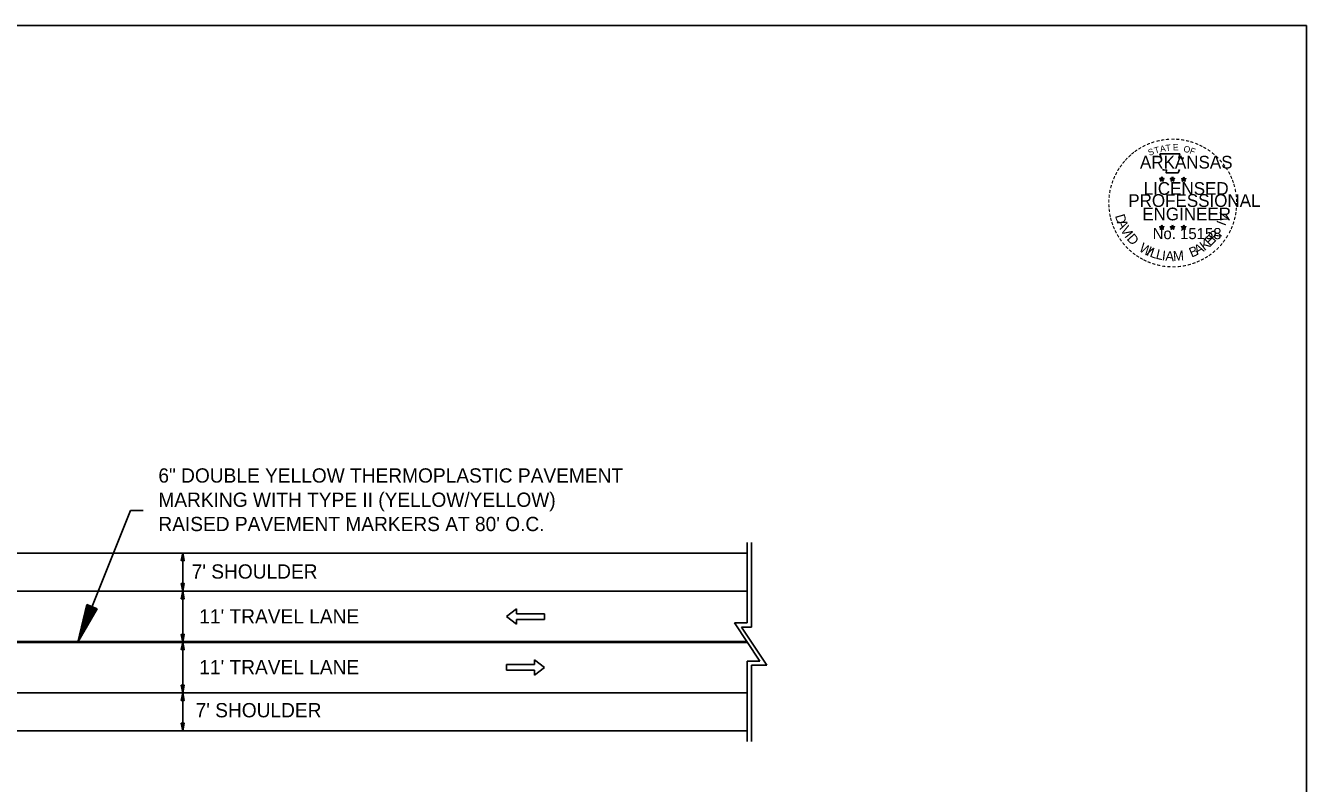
# Model space of a CAD drawing. Extents: x 1372926 to 1373096, y 381240 to 381790.
# Drawn here: x 1372995.2 to 1373096, y 381400.5 to 381460.2 of the extents above; entities that cross this region are included whole.
import ezdxf

# ---------------------------------------------------------------- set-up
doc = ezdxf.new("R2010")
doc.units = 0
for name, color, linetype in [('Default', 7, 'Continuous'), ('DSN_DRFT_Junk-No-Plot', 7, 'Continuous'), ('R_Draft', 7, 'Continuous'), ('SHET_Border-Text', 7, 'Continuous')]:
    doc.layers.add(name, color=color, linetype=linetype)

msp = doc.modelspace()

# ---------------------------------------------------------------- linework, layer by layer
at = {"layer": 'Default'}
for p, q in [((1373003.46, 381422), (1372999.31, 381411.64)), ((1373004.46, 381422), (1373003.46, 381422)), ((1373051.97, 381419.48), (1373051.97, 381413.14)), ((1373052.31, 381419.48), (1373052.31, 381412.81)), ((1373000.01, 381414.6), (1372999.31, 381411.64)), ((1373000.84, 381414.26), (1372999.31, 381411.64)), ((1373000.07, 381414.57), (1372999.49, 381412.11)), ((1373000.77, 381414.29), (1372999.49, 381412.11)), ((1373000.15, 381414.54), (1372999.68, 381412.59)), ((1373000.7, 381414.32), (1372999.68, 381412.59)), ((1373000.22, 381414.51), (1372999.87, 381413.05)), ((1373000.63, 381414.35), (1372999.87, 381413.05)), ((1373000.84, 381414.26), (1373000.01, 381414.6)), ((1373000.29, 381414.48), (1373000.06, 381413.52)), ((1373000.56, 381414.37), (1373000.06, 381413.52)), ((1373000.36, 381414.45), (1373000.25, 381413.99)), ((1373000.49, 381414.4), (1373000.25, 381413.99)), ((1373033.05, 381413.64), (1373033.82, 381414.24)), ((1373033.82, 381413.87), (1373033.82, 381414.24)), ((1373033.82, 381413.87), (1373036.03, 381413.87)), ((1373036.03, 381413.42), (1373036.03, 381413.87)), ((1373033.82, 381413.04), (1373033.05, 381413.64)), ((1373033.82, 381413.42), (1373036.03, 381413.42)), ((1373033.82, 381413.04), (1373033.82, 381413.42)), ((1373051.97, 381413.14), (1373050.97, 381413.14)), ((1373052.97, 381410.14), (1373050.97, 381413.14)), ((1373053.53, 381409.81), (1373051.53, 381412.81)), ((1373052.31, 381412.81), (1373051.53, 381412.81)), ((1373035.25, 381409.87), (1373033.05, 381409.87)), ((1373033.05, 381409.87), (1373033.05, 381409.42)), ((1373035.25, 381410.24), (1373035.25, 381409.87)), ((1373035.25, 381410.24), (1373036.03, 381409.64)), ((1373051.97, 381403.81), (1373051.97, 381410.14)), ((1373051.97, 381410.14), (1373052.97, 381410.14)), ((1373052.31, 381403.81), (1373052.31, 381409.81)), ((1373052.31, 381409.81), (1373053.53, 381409.81)), ((1373035.25, 381409.42), (1373033.05, 381409.42)), ((1373036.03, 381409.64), (1373035.25, 381409.04)), ((1373035.25, 381409.42), (1373035.25, 381409.04))]:
    msp.add_line(p, q, dxfattribs=at)
msp.add_lwpolyline([(1372925.97, 381460.17), (1372925.97, 381350.17), (1373095.97, 381350.17), (1373095.97, 381460.17)], close=True, dxfattribs=at)
at = {"layer": 'DSN_DRFT_Junk-No-Plot'}
msp.add_line((1373007.57, 381417.64), (1373007.57, 381405.64), dxfattribs=at)
for points in [[(1372925.97, 381460.17), (1373095.97, 381460.17), (1373095.97, 381350.17), (1372925.97, 381350.17)], [(1372925.97, 381460.17), (1372925.97, 381350.17), (1373095.97, 381350.17), (1373095.97, 381460.17)]]:
    msp.add_lwpolyline(points, close=True, dxfattribs=at)
for points in [[(1373007.57, 381418.65), (1373007.45, 381418.05), (1373007.69, 381418.05), (1373007.57, 381418.65), (1373007.57, 381417.45)], [(1373007.57, 381415.64), (1373007.69, 381416.24), (1373007.45, 381416.24), (1373007.57, 381415.64), (1373007.57, 381416.84)], [(1373007.57, 381415.64), (1373007.45, 381415.04), (1373007.69, 381415.04), (1373007.57, 381415.64), (1373007.57, 381414.44)], [(1373007.57, 381411.64), (1373007.69, 381412.24), (1373007.45, 381412.24), (1373007.57, 381411.64), (1373007.57, 381412.84)], [(1373007.57, 381411.64), (1373007.45, 381411.04), (1373007.69, 381411.04), (1373007.57, 381411.64), (1373007.57, 381410.44)], [(1373007.57, 381407.64), (1373007.69, 381408.24), (1373007.45, 381408.24), (1373007.57, 381407.64), (1373007.57, 381408.84)], [(1373007.57, 381407.64), (1373007.45, 381407.04), (1373007.69, 381407.04), (1373007.57, 381407.64), (1373007.57, 381406.44)], [(1373007.57, 381404.64), (1373007.69, 381405.24), (1373007.45, 381405.24), (1373007.57, 381404.64), (1373007.57, 381405.84)]]:
    msp.add_lwpolyline(points, dxfattribs=at)
at = {"layer": 'R_Draft'}
for p, q in [((1372975.58, 381418.64), (1373051.97, 381418.64)), ((1372975.58, 381415.64), (1373051.97, 381415.64)), ((1372975.55, 381411.69), (1373051.94, 381411.69)), ((1372975.62, 381411.59), (1373052.01, 381411.59)), ((1372975.58, 381407.64), (1373051.97, 381407.64)), ((1372975.58, 381404.64), (1373051.97, 381404.64))]:
    msp.add_line(p, q, dxfattribs=at)
at = {"layer": 'SHET_Border-Text'}
for p, q in [((1373084.43, 381448.13), (1373084.6, 381448.07)), ((1373084.43, 381448.13), (1373084.56, 381448.11)), ((1373084.43, 381448.13), (1373084.55, 381448.07)), ((1373084.5, 381447.93), (1373084.6, 381448.07)), ((1373084.5, 381447.93), (1373084.56, 381448.05)), ((1373084.5, 381447.93), (1373084.6, 381448.03)), ((1373084.6, 381448.26), (1373084.58, 381448.13)), ((1373084.6, 381448.07), (1373084.6, 381448.26)), ((1373084.6, 381448.26), (1373084.63, 381448.13)), ((1373084.78, 381448.13), (1373084.6, 381448.07)), ((1373084.71, 381447.93), (1373084.6, 381448.07)), ((1373084.71, 381447.93), (1373084.6, 381448.03)), ((1373084.78, 381448.13), (1373084.63, 381448.11)), ((1373084.71, 381447.93), (1373084.64, 381448.07)), ((1373084.78, 381448.13), (1373084.67, 381448.08)), ((1373085.26, 381448.13), (1373085.44, 381448.07)), ((1373085.26, 381448.13), (1373085.39, 381448.11)), ((1373085.26, 381448.13), (1373085.38, 381448.07)), ((1373085.33, 381447.93), (1373085.44, 381448.07)), ((1373085.33, 381447.93), (1373085.39, 381448.05)), ((1373085.33, 381447.93), (1373085.44, 381448.03)), ((1373085.44, 381448.26), (1373085.42, 381448.13)), ((1373085.44, 381448.07), (1373085.44, 381448.26)), ((1373085.44, 381448.26), (1373085.46, 381448.13)), ((1373085.61, 381448.13), (1373085.44, 381448.07)), ((1373085.54, 381447.93), (1373085.44, 381448.07)), ((1373085.54, 381447.93), (1373085.44, 381448.03)), ((1373085.61, 381448.13), (1373085.47, 381448.11)), ((1373085.54, 381447.93), (1373085.48, 381448.07)), ((1373085.61, 381448.13), (1373085.51, 381448.08)), ((1373086.15, 381448.12), (1373086.32, 381448.07)), ((1373086.15, 381448.12), (1373086.27, 381448.1)), ((1373086.15, 381448.12), (1373086.26, 381448.06)), ((1373086.21, 381447.92), (1373086.32, 381448.07)), ((1373086.21, 381447.92), (1373086.28, 381448.04)), ((1373086.21, 381447.92), (1373086.32, 381448.03)), ((1373086.32, 381448.25), (1373086.3, 381448.12)), ((1373086.32, 381448.07), (1373086.32, 381448.25)), ((1373086.32, 381448.25), (1373086.34, 381448.13)), ((1373086.49, 381448.12), (1373086.32, 381448.07)), ((1373086.43, 381447.92), (1373086.32, 381448.07)), ((1373086.43, 381447.92), (1373086.32, 381448.03)), ((1373086.49, 381448.12), (1373086.35, 381448.1)), ((1373086.43, 381447.92), (1373086.36, 381448.07)), ((1373086.49, 381448.12), (1373086.39, 381448.07)), ((1373084.43, 381444.34), (1373084.6, 381444.29)), ((1373084.43, 381444.34), (1373084.55, 381444.32)), ((1373084.43, 381444.34), (1373084.55, 381444.28)), ((1373084.49, 381444.14), (1373084.6, 381444.29)), ((1373084.49, 381444.14), (1373084.56, 381444.26)), ((1373084.49, 381444.14), (1373084.6, 381444.25)), ((1373084.6, 381444.47), (1373084.58, 381444.34)), ((1373084.6, 381444.29), (1373084.6, 381444.47)), ((1373084.6, 381444.47), (1373084.63, 381444.35)), ((1373084.77, 381444.34), (1373084.6, 381444.29)), ((1373084.71, 381444.14), (1373084.6, 381444.29)), ((1373084.71, 381444.14), (1373084.6, 381444.25)), ((1373084.77, 381444.34), (1373084.63, 381444.32)), ((1373084.71, 381444.14), (1373084.64, 381444.28)), ((1373084.77, 381444.34), (1373084.67, 381444.29)), ((1373085.26, 381444.34), (1373085.44, 381444.29)), ((1373085.26, 381444.34), (1373085.39, 381444.32)), ((1373085.26, 381444.34), (1373085.38, 381444.28)), ((1373085.33, 381444.14), (1373085.44, 381444.29)), ((1373085.33, 381444.14), (1373085.39, 381444.26)), ((1373085.33, 381444.14), (1373085.43, 381444.25)), ((1373085.44, 381444.47), (1373085.42, 381444.34)), ((1373085.54, 381444.14), (1373085.43, 381444.25)), ((1373085.44, 381444.29), (1373085.44, 381444.47)), ((1373085.44, 381444.47), (1373085.46, 381444.35)), ((1373085.61, 381444.34), (1373085.44, 381444.29)), ((1373085.54, 381444.14), (1373085.44, 381444.29)), ((1373085.61, 381444.34), (1373085.47, 381444.32)), ((1373085.54, 381444.14), (1373085.47, 381444.28)), ((1373085.61, 381444.34), (1373085.51, 381444.29)), ((1373086.14, 381444.34), (1373086.32, 381444.28)), ((1373086.14, 381444.34), (1373086.27, 381444.32)), ((1373086.14, 381444.34), (1373086.26, 381444.28)), ((1373086.21, 381444.13), (1373086.32, 381444.28)), ((1373086.21, 381444.13), (1373086.27, 381444.26)), ((1373086.21, 381444.13), (1373086.32, 381444.24)), ((1373086.32, 381444.47), (1373086.3, 381444.34)), ((1373086.32, 381444.28), (1373086.32, 381444.47)), ((1373086.32, 381444.47), (1373086.34, 381444.34)), ((1373086.49, 381444.34), (1373086.32, 381444.28)), ((1373086.43, 381444.13), (1373086.32, 381444.28)), ((1373086.43, 381444.13), (1373086.32, 381444.24)), ((1373086.49, 381444.34), (1373086.35, 381444.31)), ((1373086.43, 381444.13), (1373086.36, 381444.28)), ((1373086.49, 381444.34), (1373086.39, 381444.29))]:
    msp.add_line(p, q, dxfattribs=at)
for points in [[(1373084.45, 381450.07), (1373084.58, 381449.66)], [(1373086.2, 381449.61), (1373086.28, 381449.75), (1373085.93, 381449.74), (1373086.01, 381450.07), (1373084.45, 381450.07)], [(1373084.6, 381448.26), (1373084.71, 381447.93), (1373084.43, 381448.13), (1373084.78, 381448.13), (1373084.5, 381447.93), (1373084.6, 381448.26)], [(1373084.7, 381448.86), (1373084.7, 381448.81), (1373084.98, 381448.8), (1373084.95, 381448.57), (1373085.88, 381448.57), (1373085.99, 381448.84)], [(1373085.44, 381448.26), (1373085.54, 381447.93), (1373085.26, 381448.13), (1373085.61, 381448.13), (1373085.33, 381447.93), (1373085.44, 381448.26)], [(1373086.32, 381448.25), (1373086.43, 381447.92), (1373086.15, 381448.12), (1373086.49, 381448.12), (1373086.21, 381447.92), (1373086.32, 381448.25)], [(1373084.6, 381444.47), (1373084.71, 381444.14), (1373084.43, 381444.34), (1373084.77, 381444.34), (1373084.49, 381444.14), (1373084.6, 381444.47)], [(1373085.44, 381444.47), (1373085.54, 381444.14), (1373085.26, 381444.34), (1373085.61, 381444.34), (1373085.33, 381444.14), (1373085.44, 381444.47)], [(1373086.32, 381444.47), (1373086.43, 381444.13), (1373086.14, 381444.34), (1373086.49, 381444.34), (1373086.21, 381444.13), (1373086.32, 381444.47)]]:
    msp.add_lwpolyline(points, dxfattribs=at)
for centre, radius in [((1373084.6, 381448.07), 0.0861), ((1373084.6, 381448.07), 0.0723), ((1373084.6, 381448.07), 0.0579), ((1373084.6, 381448.07), 0.0495), ((1373084.6, 381448.07), 0.0374), ((1373084.6, 381448.07), 0.0248), ((1373084.6, 381448.07), 0.0148), ((1373085.44, 381448.07), 0.0861), ((1373085.44, 381448.07), 0.0723), ((1373085.44, 381448.07), 0.0579), ((1373085.44, 381448.07), 0.0495), ((1373085.44, 381448.07), 0.0374), ((1373085.44, 381448.07), 0.0248), ((1373085.44, 381448.07), 0.0148), ((1373086.32, 381448.07), 0.0861), ((1373086.32, 381448.07), 0.0723), ((1373086.32, 381448.07), 0.0579), ((1373086.32, 381448.07), 0.0495), ((1373086.32, 381448.07), 0.0374), ((1373086.32, 381448.07), 0.0248), ((1373086.32, 381448.07), 0.0148), ((1373084.6, 381444.29), 0.0861), ((1373084.6, 381444.29), 0.0723), ((1373084.6, 381444.29), 0.0579), ((1373084.6, 381444.29), 0.0495), ((1373084.6, 381444.29), 0.0374), ((1373084.6, 381444.29), 0.0248), ((1373084.6, 381444.29), 0.0148), ((1373085.44, 381444.29), 0.0861), ((1373085.44, 381444.29), 0.0723), ((1373085.44, 381444.29), 0.0579), ((1373085.44, 381444.29), 0.0495), ((1373085.44, 381444.29), 0.0374), ((1373085.44, 381444.29), 0.0248), ((1373085.44, 381444.29), 0.0148), ((1373086.32, 381444.28), 0.0861), ((1373086.32, 381444.28), 0.0723), ((1373086.32, 381444.28), 0.0579), ((1373086.32, 381444.28), 0.0495), ((1373086.32, 381444.28), 0.0374), ((1373086.32, 381444.28), 0.0248), ((1373086.32, 381444.28), 0.0148)]:
    msp.add_circle(centre, radius, dxfattribs=at)

# ---------------------------------------------------------------- texts
at = {"layer": 'Default'}
for s, p in [('6" DOUBLE YELLOW THERMOPLASTIC PAVEMENT', (1373005.65, 381424.19)), ('MARKING WITH TYPE II (YELLOW/YELLOW)', (1373005.65, 381422.28)), ("RAISED PAVEMENT MARKERS AT 80' O.C.", (1373005.65, 381420.37))]:
    msp.add_text(s, height=1.125, dxfattribs=at).set_placement(p)
at = {"layer": 'R_Draft'}
for s, p in [("7' SHOULDER", (1373008.27, 381416.63)), ("11' TRAVEL LANE", (1373008.87, 381413.1)), ("11' TRAVEL LANE", (1373008.87, 381409.1)), ("7' SHOULDER", (1373008.58, 381405.71))]:
    msp.add_text(s, height=1.125, dxfattribs=at).set_placement(p)
at = {"layer": 'SHET_Border-Text'}
for s, height, rotation, p in [('-', 0.8, 19.1761, (1373083.82, 381450.63)), ('-', 0.8, 13.6302, (1373084.2, 381450.75)), ('-', 0.8, 10.2193, (1373084.54, 381450.83)), ('-', 0.8, 5.8968, (1373084.9, 381450.89)), ('-', 0.8, 0.1862, (1373085.29, 381450.92)), ('-', 0.8, 357.743, (1373085.65, 381450.92)), ('-', 0.8, 352.1617, (1373086.02, 381450.89)), ('-', 0.8, 347.2049, (1373086.38, 381450.83)), ('-', 0.8, 342.3362, (1373086.7, 381450.76)), ('-', 0.8, 42.9622, (1373082.15, 381449.56)), ('-', 0.8, 38.9507, (1373082.36, 381449.77)), ('-', 0.8, 36.2317, (1373082.6, 381449.96)), ('-', 0.8, 34.0636, (1373082.89, 381450.15)), ('-', 0.8, 28.7918, (1373083.19, 381450.34)), ('-', 0.8, 24.3072, (1373083.51, 381450.5)), ('S', 0.5, 21.594, (1373083.63, 381449.91)), ('T', 0.5, 16.4036, (1373084.08, 381450.07)), ('A', 0.5, 11.2132, (1373084.5, 381450.2)), ('T', 0.5, 6.0228, (1373084.92, 381450.28)), ('E', 0.5, 0.8323, (1373085.47, 381450.34)), ('O', 0.5, 350.4515, (1373086.28, 381450.23)), ('F', 0.5, 340.0707, (1373086.75, 381450.12)), ('-', 0.8, 337.8551, (1373087.07, 381450.64)), ('-', 0.8, 334.1211, (1373087.38, 381450.51)), ('-', 0.8, 329.6409, (1373087.67, 381450.37)), ('-', 0.8, 325.8627, (1373087.99, 381450.19)), ('-', 0.8, 320.5297, (1373088.3, 381449.97)), ('-', 0.8, 58.0706, (1373081.35, 381448.53)), ('-', 0.8, 54.2325, (1373081.52, 381448.79)), ('-', 0.8, 50.6142, (1373081.72, 381449.08)), ('-', 0.8, 48.4231, (1373081.92, 381449.32)), ('-', 0.8, 315.5786, (1373088.6, 381449.73)), ('-', 0.8, 309.8797, (1373088.88, 381449.45)), ('-', 0.8, 306.6522, (1373089.14, 381449.15)), ('-', 0.7, 303.6753, (1373089.39, 381448.87)), ('-', 0.8, 72.3945, (1373080.96, 381447.6)), ('-', 0.8, 67.7743, (1373081.07, 381447.92)), ('-', 0.8, 62.8713, (1373081.2, 381448.22)), ('-', 0.8, 299.6684, (1373089.55, 381448.57)), ('-', 0.8, 294.6628, (1373089.71, 381448.26)), ('-', 0.8, 290.5728, (1373089.84, 381447.97)), ('-', 0.8, 81.2013, (1373080.79, 381446.89)), ('-', 0.8, 75.461, (1373080.86, 381447.25)), ('-', 0.8, 285.1233, (1373089.95, 381447.68)), ('-', 0.8, 280.5493, (1373090.05, 381447.31)), ('-', 0.8, 94.1959, (1373080.76, 381445.83)), ('-', 0.8, 89.0622, (1373080.74, 381446.19)), ('-', 0.8, 85.1863, (1373080.75, 381446.54)), ('-', 0.8, 276.5962, (1373090.13, 381446.93)), ('-', 0.8, 274.3301, (1373090.16, 381446.57)), ('-', 0.8, 269.9407, (1373090.18, 381446.25)), ('-', 0.8, 98.9479, (1373080.8, 381445.5)), ('-', 0.8, 101.7149, (1373080.86, 381445.13)), ('-', 0.8, 105.4578, (1373080.94, 381444.83)), ('D', 0.77, 286.2848, (1373080.91, 381445.2)), ('V', 0.77, 72.6573, (1373089.7, 381444.62)), ('-', 0.8, 255.7626, (1373090.08, 381445.25)), ('-', 0.8, 260.9953, (1373090.14, 381445.59)), ('-', 0.8, 263.5172, (1373090.17, 381445.92)), ('-', 0.8, 109.0874, (1373081.05, 381444.52)), ('-', 0.8, 114.0643, (1373081.18, 381444.22)), ('-', 0.8, 115.7289, (1373081.33, 381443.91)), ('A', 0.77, 292.7835, (1373081.05, 381444.7)), ('V', 0.77, 300.7936, (1373081.31, 381444.11)), ('I', 0.77, 308.3502, (1373081.63, 381443.59)), ('R', 0.77, 50.3651, (1373088.77, 381443.11)), ('I', 0.77, 69.0301, (1373089.59, 381444.35)), ('-', 0.8, 244.6197, (1373089.75, 381444.24)), ('-', 0.8, 247.8887, (1373089.88, 381444.55)), ('-', 0.8, 252.8681, (1373089.99, 381444.89)), ('-', 0.8, 120.4471, (1373081.51, 381443.62)), ('-', 0.8, 125.8934, (1373081.71, 381443.34)), ('-', 0.8, 130.7181, (1373081.94, 381443.06)), ('D', 0.77, 311.9774, (1373081.8, 381443.36)), ('W', 0.77, 328.0731, (1373082.74, 381442.47)), ('A', 0.77, 28.9042, (1373087.39, 381442.09)), ('K', 0.77, 36.9143, (1373087.95, 381442.41)), ('E', 0.77, 44.0175, (1373088.4, 381442.75)), (',', 0.77, 57.4684, (1373089.13, 381443.55)), ('-', 0.8, 231.2538, (1373089.14, 381443.25)), ('-', 0.8, 233.8452, (1373089.35, 381443.54)), ('-', 0.8, 239.0712, (1373089.55, 381443.86)), ('-', 0.8, 134.2238, (1373082.2, 381442.79)), ('-', 0.8, 138.9338, (1373082.46, 381442.56)), ('-', 0.8, 144.6463, (1373082.74, 381442.35)), ('-', 0.8, 148.0898, (1373083.02, 381442.17)), ('-', 0.8, 151.5704, (1373083.31, 381442.01)), ('I', 0.77, 336.6877, (1373083.33, 381442.12)), ('L', 0.77, 340.3149, (1373083.6, 381442)), ('L', 0.77, 346.6625, (1373084.08, 381441.83)), ('I', 0.77, 353.0101, (1373084.58, 381441.71)), ('A', 0.77, 356.6373, (1373084.86, 381441.66)), ('M', 0.77, 4.6473, (1373085.51, 381441.64)), ('B', 0.77, 22.8589, (1373086.94, 381441.9)), ('-', 0.8, 212.2491, (1373088.09, 381442.29)), ('-', 0.8, 215.7363, (1373088.36, 381442.48)), ('-', 0.8, 221.0851, (1373088.63, 381442.72)), ('-', 0.8, 225.7653, (1373088.9, 381442.97)), ('-', 0.8, 154.6002, (1373083.57, 381441.88)), ('-', 0.8, 158.5612, (1373083.88, 381441.76)), ('-', 0.8, 162.7983, (1373084.23, 381441.65)), ('-', 0.8, 167.5555, (1373084.59, 381441.57)), ('-', 0.8, 173.1155, (1373084.97, 381441.51)), ('-', 0.8, 176.5183, (1373085.35, 381441.49)), ('-', 0.8, 181.5918, (1373085.72, 381441.49)), ('-', 0.8, 185.8167, (1373086.12, 381441.53)), ('-', 0.8, 191.2858, (1373086.49, 381441.6)), ('-', 0.8, 195.4743, (1373086.85, 381441.7)), ('-', 0.8, 199.4643, (1373087.19, 381441.82)), ('-', 0.8, 204.2516, (1373087.5, 381441.96)), ('-', 0.8, 207.3568, (1373087.81, 381442.12))]:
    msp.add_text(s, height=height, rotation=rotation, dxfattribs=at).set_placement(p)
for s, height, p in [('ARKANSAS', 1, (1373082.88, 381448.92)), ('LICENSED', 1, (1373083.17, 381446.85)), ('PROFESSIONAL', 1, (1373081.96, 381445.9)), ('ENGINEER', 1, (1373083.06, 381444.84)), ('No. 15158', 0.878, (1373083.88, 381443.36)), ('AAMU', 0.00001, (1373085.4, 381441.63))]:
    msp.add_text(s, height=height, dxfattribs=at).set_placement(p)

doc.saveas('drawing.dxf')
